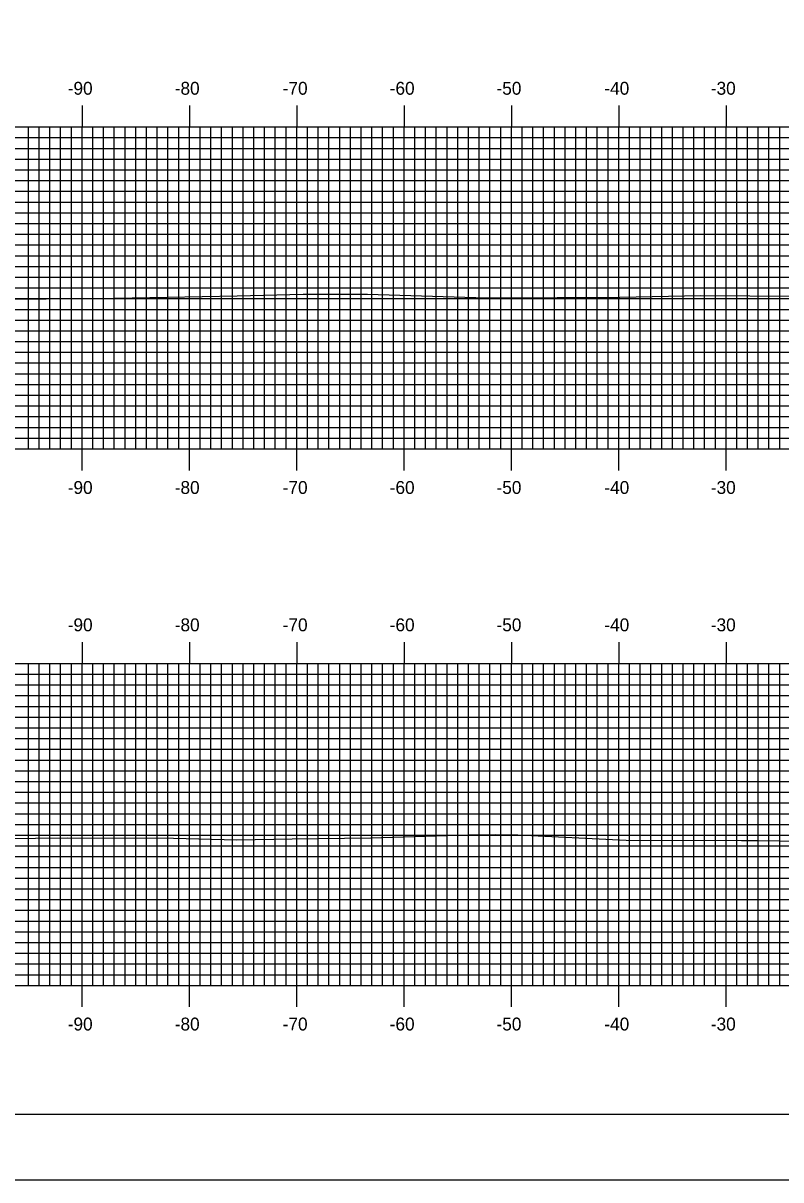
# Model space of a CAD drawing. Extents: x 854510 to 854853, y 364366 to 364586.
# Drawn here: x 854580.2 to 854650.8, y 364365.7 to 364473.5 of the extents above; entities that cross this region are included whole.
import ezdxf

# ---------------------------------------------------------------- set-up
doc = ezdxf.new("R2010")
doc.units = 0
for name, color, linetype in [('BORDER', 7, 'Continuous'), ('H_V ANNOTATION', 7, 'Continuous'), ('MAJOR', 7, 'Continuous'), ('MINOR', 7, 'Continuous'), ('PLOT BOUNDARY', 7, 'Continuous'), ('S_Roadway_Centerline', 7, 'Continuous')]:
    doc.layers.add(name, color=color, linetype=linetype)

msp = doc.modelspace()

# ---------------------------------------------------------------- linework, layer by layer
at = {"layer": 'BORDER'}
msp.add_lwpolyline([(854526.14, 364371.79), (854846.14, 364371.79), (854846.14, 364581.79), (854526.14, 364581.79)], close=True, dxfattribs=at)
at = {"layer": 'MAJOR'}
for p, q in [((854585.74, 364465.79), (854585.74, 364463.79)), ((854595.74, 364465.79), (854595.74, 364463.79)), ((854605.74, 364465.79), (854605.74, 364463.79)), ((854615.74, 364465.79), (854615.74, 364463.79)), ((854625.74, 364465.79), (854625.74, 364463.79)), ((854635.74, 364465.79), (854635.74, 364463.79)), ((854645.74, 364465.79), (854645.74, 364463.79)), ((854535.74, 364463.79), (854815.74, 364463.79)), ((854535.74, 364463.79), (854815.74, 364463.79)), ((854585.74, 364433.79), (854585.74, 364463.79)), ((854595.74, 364433.79), (854595.74, 364463.79)), ((854605.74, 364433.79), (854605.74, 364463.79)), ((854615.74, 364433.79), (854615.74, 364463.79)), ((854625.74, 364433.79), (854625.74, 364463.79)), ((854635.74, 364433.79), (854635.74, 364463.79)), ((854645.74, 364433.79), (854645.74, 364463.79)), ((854535.74, 364458.79), (854815.74, 364458.79)), ((854535.74, 364453.79), (854815.74, 364453.79)), ((854535.74, 364448.79), (854815.74, 364448.79)), ((854535.74, 364443.79), (854815.74, 364443.79)), ((854535.74, 364438.79), (854815.74, 364438.79)), ((854535.74, 364433.79), (854815.74, 364433.79)), ((854535.74, 364433.79), (854815.74, 364433.79)), ((854585.74, 364431.78), (854585.74, 364433.79)), ((854595.74, 364431.78), (854595.74, 364433.79)), ((854605.74, 364431.78), (854605.74, 364433.79)), ((854615.74, 364431.78), (854615.74, 364433.79)), ((854625.74, 364431.78), (854625.74, 364433.79)), ((854635.74, 364431.78), (854635.74, 364433.79)), ((854645.74, 364431.78), (854645.74, 364433.79)), ((854585.74, 364415.79), (854585.74, 364413.79)), ((854595.74, 364415.79), (854595.74, 364413.79)), ((854605.74, 364415.79), (854605.74, 364413.79)), ((854615.74, 364415.79), (854615.74, 364413.79)), ((854625.74, 364415.79), (854625.74, 364413.79)), ((854635.74, 364415.79), (854635.74, 364413.79)), ((854645.74, 364415.79), (854645.74, 364413.79)), ((854535.74, 364413.79), (854815.74, 364413.79)), ((854535.74, 364413.79), (854815.74, 364413.79)), ((854585.74, 364383.79), (854585.74, 364413.79)), ((854595.74, 364383.79), (854595.74, 364413.79)), ((854605.74, 364383.79), (854605.74, 364413.79)), ((854615.74, 364383.79), (854615.74, 364413.79)), ((854625.74, 364383.79), (854625.74, 364413.79)), ((854635.74, 364383.79), (854635.74, 364413.79)), ((854645.74, 364383.79), (854645.74, 364413.79)), ((854535.74, 364408.79), (854815.74, 364408.79)), ((854535.74, 364403.79), (854815.74, 364403.79)), ((854535.74, 364398.79), (854815.74, 364398.79)), ((854535.74, 364393.79), (854815.74, 364393.79)), ((854535.74, 364388.79), (854815.74, 364388.79)), ((854535.74, 364383.79), (854815.74, 364383.79)), ((854535.74, 364383.79), (854815.74, 364383.79)), ((854585.74, 364381.78), (854585.74, 364383.79)), ((854595.74, 364381.78), (854595.74, 364383.79)), ((854605.74, 364381.78), (854605.74, 364383.79)), ((854615.74, 364381.78), (854615.74, 364383.79)), ((854625.74, 364381.78), (854625.74, 364383.79)), ((854635.74, 364381.78), (854635.74, 364383.79)), ((854645.74, 364381.78), (854645.74, 364383.79))]:
    msp.add_line(p, q, dxfattribs=at)
at = {"layer": 'MINOR'}
for p, q in [((854580.74, 364433.79), (854580.74, 364463.79)), ((854581.74, 364433.79), (854581.74, 364463.79)), ((854582.74, 364433.79), (854582.74, 364463.79)), ((854583.74, 364433.79), (854583.74, 364463.79)), ((854584.74, 364433.79), (854584.74, 364463.79)), ((854586.74, 364433.79), (854586.74, 364463.79)), ((854587.74, 364433.79), (854587.74, 364463.79)), ((854588.74, 364433.79), (854588.74, 364463.79)), ((854589.74, 364433.79), (854589.74, 364463.79)), ((854590.74, 364433.79), (854590.74, 364463.79)), ((854591.74, 364433.79), (854591.74, 364463.79)), ((854592.74, 364433.79), (854592.74, 364463.79)), ((854593.74, 364433.79), (854593.74, 364463.79)), ((854594.74, 364433.79), (854594.74, 364463.79)), ((854596.74, 364433.79), (854596.74, 364463.79)), ((854597.74, 364433.79), (854597.74, 364463.79)), ((854598.74, 364433.79), (854598.74, 364463.79)), ((854599.74, 364433.79), (854599.74, 364463.79)), ((854600.74, 364433.79), (854600.74, 364463.79)), ((854601.74, 364433.79), (854601.74, 364463.79)), ((854602.74, 364433.79), (854602.74, 364463.79)), ((854603.74, 364433.79), (854603.74, 364463.79)), ((854604.74, 364433.79), (854604.74, 364463.79)), ((854606.74, 364433.79), (854606.74, 364463.79)), ((854607.74, 364433.79), (854607.74, 364463.79)), ((854608.74, 364433.79), (854608.74, 364463.79)), ((854609.74, 364433.79), (854609.74, 364463.79)), ((854610.74, 364433.79), (854610.74, 364463.79)), ((854611.74, 364433.79), (854611.74, 364463.79)), ((854612.74, 364433.79), (854612.74, 364463.79)), ((854613.74, 364433.79), (854613.74, 364463.79)), ((854614.74, 364433.79), (854614.74, 364463.79)), ((854616.74, 364433.79), (854616.74, 364463.79)), ((854617.74, 364433.79), (854617.74, 364463.79)), ((854618.74, 364433.79), (854618.74, 364463.79)), ((854619.74, 364433.79), (854619.74, 364463.79)), ((854620.74, 364433.79), (854620.74, 364463.79)), ((854621.74, 364433.79), (854621.74, 364463.79)), ((854622.74, 364433.79), (854622.74, 364463.79)), ((854623.74, 364433.79), (854623.74, 364463.79)), ((854624.74, 364433.79), (854624.74, 364463.79)), ((854626.74, 364433.79), (854626.74, 364463.79)), ((854627.74, 364433.79), (854627.74, 364463.79)), ((854628.74, 364433.79), (854628.74, 364463.79)), ((854629.74, 364433.79), (854629.74, 364463.79)), ((854630.74, 364433.79), (854630.74, 364463.79)), ((854631.74, 364433.79), (854631.74, 364463.79)), ((854632.74, 364433.79), (854632.74, 364463.79)), ((854633.74, 364433.79), (854633.74, 364463.79)), ((854634.74, 364433.79), (854634.74, 364463.79)), ((854636.74, 364433.79), (854636.74, 364463.79)), ((854637.74, 364433.79), (854637.74, 364463.79)), ((854638.74, 364433.79), (854638.74, 364463.79)), ((854639.74, 364433.79), (854639.74, 364463.79)), ((854640.74, 364433.79), (854640.74, 364463.79)), ((854641.74, 364433.79), (854641.74, 364463.79)), ((854642.74, 364433.79), (854642.74, 364463.79)), ((854643.74, 364433.79), (854643.74, 364463.79)), ((854644.74, 364433.79), (854644.74, 364463.79)), ((854646.74, 364433.79), (854646.74, 364463.79)), ((854647.74, 364433.79), (854647.74, 364463.79)), ((854648.74, 364433.79), (854648.74, 364463.79)), ((854649.74, 364433.79), (854649.74, 364463.79)), ((854650.74, 364433.79), (854650.74, 364463.79)), ((854535.74, 364462.79), (854815.74, 364462.79)), ((854535.74, 364461.79), (854815.74, 364461.79)), ((854535.74, 364460.79), (854815.74, 364460.79)), ((854535.74, 364459.79), (854815.74, 364459.79)), ((854535.74, 364457.79), (854815.74, 364457.79)), ((854535.74, 364456.79), (854815.74, 364456.79)), ((854535.74, 364455.79), (854815.74, 364455.79)), ((854535.74, 364454.79), (854815.74, 364454.79)), ((854535.74, 364452.79), (854815.74, 364452.79)), ((854535.74, 364451.79), (854815.74, 364451.79)), ((854535.74, 364450.79), (854815.74, 364450.79)), ((854535.74, 364449.79), (854815.74, 364449.79)), ((854535.74, 364447.79), (854815.74, 364447.79)), ((854535.74, 364446.79), (854815.74, 364446.79)), ((854535.74, 364445.79), (854815.74, 364445.79)), ((854535.74, 364444.79), (854815.74, 364444.79)), ((854535.74, 364442.79), (854815.74, 364442.79)), ((854535.74, 364441.79), (854815.74, 364441.79)), ((854535.74, 364440.79), (854815.74, 364440.79)), ((854535.74, 364439.79), (854815.74, 364439.79)), ((854535.74, 364437.79), (854815.74, 364437.79)), ((854535.74, 364436.79), (854815.74, 364436.79)), ((854535.74, 364435.79), (854815.74, 364435.79)), ((854535.74, 364434.79), (854815.74, 364434.79)), ((854580.74, 364383.79), (854580.74, 364413.79)), ((854581.74, 364383.79), (854581.74, 364413.79)), ((854582.74, 364383.79), (854582.74, 364413.79)), ((854583.74, 364383.79), (854583.74, 364413.79)), ((854584.74, 364383.79), (854584.74, 364413.79)), ((854586.74, 364383.79), (854586.74, 364413.79)), ((854587.74, 364383.79), (854587.74, 364413.79)), ((854588.74, 364383.79), (854588.74, 364413.79)), ((854589.74, 364383.79), (854589.74, 364413.79)), ((854590.74, 364383.79), (854590.74, 364413.79)), ((854591.74, 364383.79), (854591.74, 364413.79)), ((854592.74, 364383.79), (854592.74, 364413.79)), ((854593.74, 364383.79), (854593.74, 364413.79)), ((854594.74, 364383.79), (854594.74, 364413.79)), ((854596.74, 364383.79), (854596.74, 364413.79)), ((854597.74, 364383.79), (854597.74, 364413.79)), ((854598.74, 364383.79), (854598.74, 364413.79)), ((854599.74, 364383.79), (854599.74, 364413.79)), ((854600.74, 364383.79), (854600.74, 364413.79)), ((854601.74, 364383.79), (854601.74, 364413.79)), ((854602.74, 364383.79), (854602.74, 364413.79)), ((854603.74, 364383.79), (854603.74, 364413.79)), ((854604.74, 364383.79), (854604.74, 364413.79)), ((854606.74, 364383.79), (854606.74, 364413.79)), ((854607.74, 364383.79), (854607.74, 364413.79)), ((854608.74, 364383.79), (854608.74, 364413.79)), ((854609.74, 364383.79), (854609.74, 364413.79)), ((854610.74, 364383.79), (854610.74, 364413.79)), ((854611.74, 364383.79), (854611.74, 364413.79)), ((854612.74, 364383.79), (854612.74, 364413.79)), ((854613.74, 364383.79), (854613.74, 364413.79)), ((854614.74, 364383.79), (854614.74, 364413.79)), ((854616.74, 364383.79), (854616.74, 364413.79)), ((854617.74, 364383.79), (854617.74, 364413.79)), ((854618.74, 364383.79), (854618.74, 364413.79)), ((854619.74, 364383.79), (854619.74, 364413.79)), ((854620.74, 364383.79), (854620.74, 364413.79)), ((854621.74, 364383.79), (854621.74, 364413.79)), ((854622.74, 364383.79), (854622.74, 364413.79)), ((854623.74, 364383.79), (854623.74, 364413.79)), ((854624.74, 364383.79), (854624.74, 364413.79)), ((854626.74, 364383.79), (854626.74, 364413.79)), ((854627.74, 364383.79), (854627.74, 364413.79)), ((854628.74, 364383.79), (854628.74, 364413.79)), ((854629.74, 364383.79), (854629.74, 364413.79)), ((854630.74, 364383.79), (854630.74, 364413.79)), ((854631.74, 364383.79), (854631.74, 364413.79)), ((854632.74, 364383.79), (854632.74, 364413.79)), ((854633.74, 364383.79), (854633.74, 364413.79)), ((854634.74, 364383.79), (854634.74, 364413.79)), ((854636.74, 364383.79), (854636.74, 364413.79)), ((854637.74, 364383.79), (854637.74, 364413.79)), ((854638.74, 364383.79), (854638.74, 364413.79)), ((854639.74, 364383.79), (854639.74, 364413.79)), ((854640.74, 364383.79), (854640.74, 364413.79)), ((854641.74, 364383.79), (854641.74, 364413.79)), ((854642.74, 364383.79), (854642.74, 364413.79)), ((854643.74, 364383.79), (854643.74, 364413.79)), ((854644.74, 364383.79), (854644.74, 364413.79)), ((854646.74, 364383.79), (854646.74, 364413.79)), ((854647.74, 364383.79), (854647.74, 364413.79)), ((854648.74, 364383.79), (854648.74, 364413.79)), ((854649.74, 364383.79), (854649.74, 364413.79)), ((854650.74, 364383.79), (854650.74, 364413.79)), ((854535.74, 364412.79), (854815.74, 364412.79)), ((854535.74, 364411.79), (854815.74, 364411.79)), ((854535.74, 364410.79), (854815.74, 364410.79)), ((854535.74, 364409.79), (854815.74, 364409.79)), ((854535.74, 364407.79), (854815.74, 364407.79)), ((854535.74, 364406.79), (854815.74, 364406.79)), ((854535.74, 364405.79), (854815.74, 364405.79)), ((854535.74, 364404.79), (854815.74, 364404.79)), ((854535.74, 364402.79), (854815.74, 364402.79)), ((854535.74, 364401.79), (854815.74, 364401.79)), ((854535.74, 364400.79), (854815.74, 364400.79)), ((854535.74, 364399.79), (854815.74, 364399.79)), ((854535.74, 364397.79), (854815.74, 364397.79)), ((854535.74, 364396.79), (854815.74, 364396.79)), ((854535.74, 364395.79), (854815.74, 364395.79)), ((854535.74, 364394.79), (854815.74, 364394.79)), ((854535.74, 364392.79), (854815.74, 364392.79)), ((854535.74, 364391.79), (854815.74, 364391.79)), ((854535.74, 364390.79), (854815.74, 364390.79)), ((854535.74, 364389.79), (854815.74, 364389.79)), ((854535.74, 364387.79), (854815.74, 364387.79)), ((854535.74, 364386.79), (854815.74, 364386.79)), ((854535.74, 364385.79), (854815.74, 364385.79)), ((854535.74, 364384.79), (854815.74, 364384.79))]:
    msp.add_line(p, q, dxfattribs=at)
at = {"layer": 'PLOT BOUNDARY'}
msp.add_lwpolyline([(854509.96, 364365.67), (854849.96, 364365.67), (854849.96, 364585.67), (854509.96, 364585.67)], close=True, dxfattribs=at)
at = {"layer": 'S_Roadway_Centerline'}
for points in [[(854535.74, 364448.34), (854539.56, 364448.34), (854550.22, 364448.27), (854554.82, 364448.12), (854568.37, 364447.66), (854585.89, 364447.79), (854586.57, 364447.8), (854587.15, 364447.81), (854600.18, 364448.06), (854606.34, 364448.19), (854612.32, 364448.2), (854623.42, 364447.86), (854624.15, 364447.85), (854635.84, 364447.92), (854643.39, 364448.07), (854657.11, 364448)], [(854535.74, 364396.63), (854538.88, 364396.67), (854541.23, 364396.71), (854543.13, 364396.78), (854554.57, 364397.09), (854565.33, 364397.32), (854565.94, 364397.33), (854566.66, 364397.34), (854584.35, 364397.55), (854594.24, 364397.5), (854600.17, 364397.36), (854605.32, 364397.46), (854612.64, 364397.54), (854621.71, 364397.82), (854624.26, 364397.84), (854626.35, 364397.81), (854636.42, 364397.33), (854647.19, 364397.3), (854648.75, 364397.28), (854668.36, 364396.97)]]:
    msp.add_lwpolyline(points, dxfattribs=at)

# ---------------------------------------------------------------- texts
at = {"layer": 'H_V ANNOTATION'}
for s, p in [('-90', (854584.4, 364466.79)), ('-80', (854594.37, 364466.79)), ('-70', (854604.43, 364466.79)), ('-60', (854614.4, 364466.79)), ('-50', (854624.35, 364466.79)), ('-40', (854634.4, 364466.79)), ('-30', (854644.32, 364466.79)), ('-90', (854584.4, 364429.59)), ('-80', (854594.37, 364429.59)), ('-70', (854604.43, 364429.59)), ('-60', (854614.4, 364429.59)), ('-50', (854624.35, 364429.59)), ('-40', (854634.4, 364429.59)), ('-30', (854644.32, 364429.59)), ('-90', (854584.4, 364416.79)), ('-80', (854594.37, 364416.79)), ('-70', (854604.43, 364416.79)), ('-60', (854614.4, 364416.79)), ('-50', (854624.35, 364416.79)), ('-40', (854634.4, 364416.79)), ('-30', (854644.32, 364416.79)), ('-90', (854584.4, 364379.59)), ('-80', (854594.37, 364379.59)), ('-70', (854604.43, 364379.59)), ('-60', (854614.4, 364379.59)), ('-50', (854624.35, 364379.59)), ('-40', (854634.4, 364379.59)), ('-30', (854644.32, 364379.59))]:
    msp.add_text(s, height=1.2, dxfattribs=at).set_placement(p)

doc.saveas('drawing.dxf')
